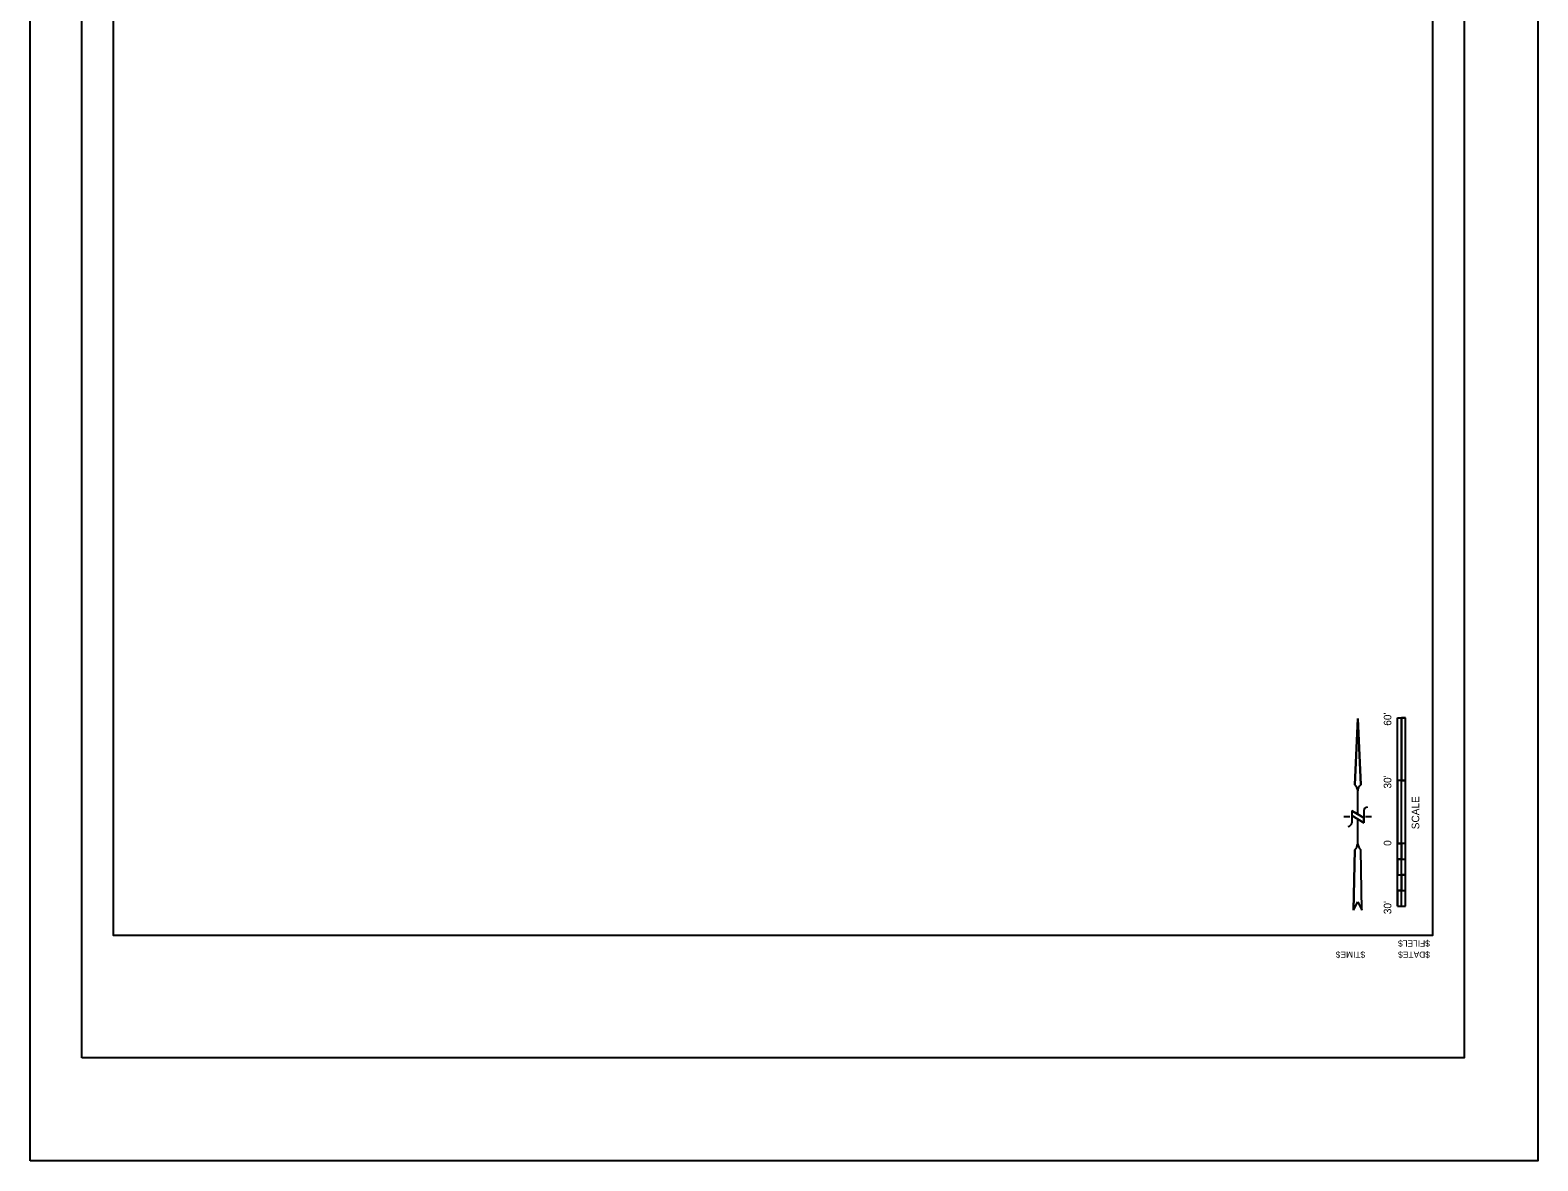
# Model space of a CAD drawing. Extents: x 2150652 to 2151372, y 143470 to 144550.
# Drawn here: x 2150652 to 2151372, y 143470 to 144010 of the extents above; entities that cross this region are included whole.
import ezdxf

# ---------------------------------------------------------------- set-up
doc = ezdxf.new("R2010")
doc.units = 0
for name, color, linetype in [('EX_Align_12', 7, 'Continuous'), ('SHT_Plot_Shape_Half', 7, 'Continuous'), ('SHT_Scale', 7, 'Continuous'), ('SHT_Sheet_Border', 7, 'Continuous'), ('TOPO_Curb Back', 7, 'Continuous'), ('TOPO_Curb Gut', 7, 'Continuous')]:
    doc.layers.add(name, color=color, linetype=linetype)

msp = doc.modelspace()

# ---------------------------------------------------------------- linework, layer by layer
at = {"layer": 'EX_Align_12'}
for p, q in [((2151284.78, 143649.94), (2151286.22, 143681.67)), ((2151286.22, 143681.67), (2151284.78, 143649.94)), ((2151286.22, 143681.67), (2151287.67, 143649.94)), ((2151287.67, 143649.94), (2151286.22, 143681.67)), ((2151286.22, 143635.9), (2151286.22, 143647.13)), ((2151282.48, 143634.75), (2151279.6, 143634.75)), ((2151289.1, 143634.18), (2151283.35, 143637.63)), ((2151283.35, 143637.63), (2151289.1, 143634.18)), ((2151283.35, 143637.63), (2151283.35, 143631.87)), ((2151286.22, 143635.9), (2151283.35, 143637.63)), ((2151283.35, 143637.63), (2151283.35, 143635.33)), ((2151289.1, 143631.87), (2151283.35, 143635.33)), ((2151289.1, 143634.18), (2151286.22, 143635.9)), ((2151286.22, 143621.8), (2151286.22, 143633.6)), ((2151289.1, 143637.63), (2151289.1, 143631.87)), ((2151289.1, 143631.87), (2151289.1, 143634.18)), ((2151292.84, 143634.75), (2151289.97, 143634.75)), ((2151284.21, 143590.14), (2151284.79, 143618.92)), ((2151284.79, 143618.92), (2151284.21, 143590.14)), ((2151288.24, 143590.14), (2151287.66, 143618.92)), ((2151288.24, 143590.14), (2151287.66, 143618.92)), ((2151284.21, 143590.14), (2151286.22, 143594.17)), ((2151284.21, 143590.14), (2151286.22, 143594.17)), ((2151286.22, 143594.17), (2151288.24, 143590.14)), ((2151286.22, 143594.17), (2151288.24, 143590.14))]:
    msp.add_line(p, q, dxfattribs=at)
for points in [[(2151283.35, 143635.33), (2151286.22, 143633.6), (2151289.1, 143631.87)], [(2151286.23, 143621.8), (2151286.22, 143621.8), (2151286.22, 143621.8)]]:
    msp.add_lwpolyline(points, dxfattribs=at)
for centre, radius, start, end in [((2151282.77, 143647.13), 3.45, 0, 54.38016), ((2151282.77, 143647.13), 3.45, 0, 54.38016), ((2151289.68, 143647.13), 3.45, 125.61984, 180), ((2151289.68, 143647.13), 3.45, 125.61984, 180), ((2151290.83, 143637.63), 1.73, 90, 180), ((2151281.62, 143631.87), 1.73, 270, 0), ((2151281.21, 143622.5), 5.06, 314.95671, 352.41889), ((2151281.21, 143622.5), 5.06, 314.95671, 352.059), ((2151291.24, 143622.5), 5.06, 187.58111, 225.04329), ((2151291.24, 143622.5), 5.06, 187.941, 225.04329)]:
    msp.add_arc(centre, radius, start, end, dxfattribs=at)
at = {"layer": 'SHT_Plot_Shape_Half'}
msp.add_lwpolyline([(2150677, 143519.53), (2150677, 144539.53), (2151337, 144539.53), (2151337, 143519.53)], close=True, dxfattribs=at)
at = {"layer": 'SHT_Scale'}
for p, q in [((2151305.27, 143682.01), (2151307.14, 143682.01)), ((2151305.27, 143592.01), (2151305.27, 143682.01)), ((2151307.14, 143682.01), (2151309.02, 143682.01)), ((2151307.14, 143622.01), (2151307.14, 143682.01)), ((2151309.02, 143682.01), (2151307.14, 143682.01)), ((2151307.14, 143682.01), (2151307.14, 143652.01)), ((2151309.02, 143592.01), (2151309.02, 143682.01)), ((2151309.02, 143652.01), (2151309.02, 143682.01)), ((2151307.14, 143652.01), (2151305.27, 143652.01)), ((2151307.14, 143652.01), (2151305.27, 143652.01)), ((2151305.27, 143652.01), (2151305.27, 143622.01)), ((2151309.02, 143652.01), (2151307.14, 143652.01)), ((2151307.14, 143622.01), (2151307.14, 143652.01)), ((2151307.14, 143652.01), (2151309.02, 143652.01)), ((2151307.14, 143622.01), (2151305.27, 143622.01)), ((2151305.27, 143622.01), (2151307.14, 143622.01)), ((2151309.02, 143622.01), (2151307.14, 143622.01)), ((2151307.14, 143614.51), (2151307.14, 143622.01)), ((2151309.02, 143622.01), (2151307.14, 143622.01)), ((2151307.14, 143622.01), (2151307.14, 143614.51)), ((2151309.02, 143614.51), (2151309.02, 143622.01)), ((2151305.27, 143614.51), (2151309.02, 143614.51)), ((2151307.14, 143614.51), (2151305.27, 143614.51)), ((2151305.27, 143614.51), (2151305.27, 143607.01)), ((2151307.14, 143607.01), (2151307.14, 143614.51)), ((2151307.14, 143607.01), (2151307.14, 143614.51)), ((2151307.14, 143614.51), (2151309.02, 143614.51)), ((2151305.27, 143607.01), (2151309.02, 143607.01)), ((2151305.27, 143607.01), (2151309.02, 143607.01)), ((2151305.27, 143607.01), (2151307.14, 143607.01)), ((2151307.14, 143599.51), (2151307.14, 143607.01)), ((2151309.02, 143607.01), (2151307.14, 143607.01)), ((2151307.14, 143607.01), (2151307.14, 143599.51)), ((2151309.02, 143599.51), (2151309.02, 143607.01)), ((2151305.27, 143599.51), (2151309.02, 143599.51)), ((2151307.14, 143599.51), (2151305.27, 143599.51)), ((2151305.27, 143599.51), (2151305.27, 143592.01)), ((2151307.14, 143592.01), (2151307.14, 143599.51)), ((2151307.14, 143592.01), (2151307.14, 143599.51)), ((2151307.14, 143599.51), (2151309.02, 143599.51)), ((2151305.27, 143592.01), (2151309.02, 143592.01)), ((2151305.27, 143592.01), (2151307.14, 143592.01))]:
    msp.add_line(p, q, dxfattribs=at)
at = {"layer": 'SHT_Sheet_Border'}
msp.add_lwpolyline([(2151322, 144523.03), (2151322, 143578.03), (2150692, 143578.03), (2150692, 144523.03)], close=True, dxfattribs=at)
at = {"layer": 'TOPO_Curb Gut'}
msp.add_lwpolyline([(2150652.25, 143470.4), (2150652.25, 144550.4), (2151372.25, 144550.4), (2151372.25, 143470.4)], close=True, dxfattribs=at)

# ---------------------------------------------------------------- texts
at = {"layer": 'SHT_Scale'}
for s, p in [("60'", (2151302.27, 143678.2)), ("30'", (2151302.27, 143648.2)), ('SCALE', (2151315.62, 143628.76)), ('0', (2151302.27, 143620.83)), ("30'", (2151302.27, 143588.2))]:
    msp.add_text(s, height=3.6, rotation=90, dxfattribs=at).set_placement(p)
at = {"layer": 'TOPO_Curb Back'}
for s, p in [('$FILEL$', (2151320.73, 143575.71)), ('$TIME$', (2151289.83, 143570.38)), ('$DATE$', (2151320.73, 143570.38))]:
    msp.add_text(s, height=3, rotation=180, dxfattribs=at).set_placement(p)

doc.saveas('drawing.dxf')
